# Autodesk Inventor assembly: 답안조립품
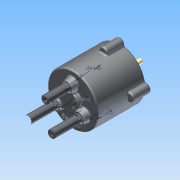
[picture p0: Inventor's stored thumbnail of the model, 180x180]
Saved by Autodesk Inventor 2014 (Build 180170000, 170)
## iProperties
Created: 2015-09
Part Number: 답안조립품
Document SubType Name: Assembly
Designer: study
Mass: 2160.28 g
Surface Area: 1801.23 cm^2
Volume: 438.526 cm^3
Density: 4.92622 g/cm^3
Author: study
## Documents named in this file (14)
- C:\Users\study\Desktop\350916V1013\답안조립품.iam
- C:\Users\study\Desktop\350916V1013\몸체.ipt
- C:\Users\study\Desktop\350916V1013\메인 축.ipt
- C:\Users\study\Desktop\350916V1013\판캠.ipt
- C:\Users\study\Desktop\350916V1013\멈춤링 22 x 1.2.ipt
- C:\Users\study\Desktop\350916V1013\멈춤링 10 x 1.ipt
- C:\Users\study\Desktop\350916V1013\베어링 NA 4900.ipt
- C:\Users\study\Desktop\350916V1013\슬라이드 축.ipt
- C:\Users\study\Desktop\350916V1013\커버.ipt
- C:\Users\study\Desktop\350916V1013\오일실.ipt
- C:\Users\study\Desktop\350916V1013\M5x0.8x20.ipt
- C:\Users\study\Desktop\350916V1013\11-가변스프링.ipt
- C:\Users\study\Desktop\350916V1013\12-가변스프링.ipt
- C:\Users\study\Desktop\350916V1013\13-가변스프링.ipt
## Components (7 placed, 4 different names)
1. 11-가변스프링:1
2. 12-가변스프링:1
3. 13-가변스프링:1
4. M5x0.8x20:1
5. M5x0.8x20:2
6. M5x0.8x20:3
7. M5x0.8x20:4
